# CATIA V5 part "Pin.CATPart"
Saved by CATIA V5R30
Part number: Pin
Bounding box of the stored display mesh (mm): x -10.997 to 10.997, y 0 to 38, z -10.885 to 10.885
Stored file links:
  D:\PROJECTS\CATIA V56R 2020\Resources\Parts File\c14_catia_v5_6r2020_prt\c14-catia-v5-6r2020-figr-14-26 & 27\Part & Asm\Pin.CATPart
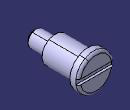
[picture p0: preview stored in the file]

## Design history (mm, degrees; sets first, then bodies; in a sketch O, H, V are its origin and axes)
Body1 (main body)
  Sketch1 on yz-plane, origin (0, 0, 0), H (0, 1, 0), V (0, 0, 1)
    line L1 (0, 0) -> (0, 5)
    line L2 (0, 5) -> (13, 5)
    line L3 (13, 5) -> (13, 8)
    line L4 (13, 8) -> (33, 8)
    line L5 (33, 8) -> (33, 11)
    line L6 (33, 11) -> (38, 11)
    line L7 (38, 11) -> (38, 0)
    point P7 (38, 0)
    line L8 (38, 0) -> (0, 0)
    distance L8 L6 = 11
    distance L4 L8 = 8
    length L8 = 38
    distance L2 L8 = 5
    length L6 = 5
    length L4 = 20
    vertical: L1 V, L3 V, L5 V, L7 V
    horizontal: L2 H, L4 H, L8 H, L6 H
    coincidence: P7 H
  Shaft1: profile Sketch1, axis edge of Sketch1, angle 360
  Chamfer1: length 1.5, angle 45, on 1 edge
  Fillet1: radius 1.5, on 1 edge
  Sketch2 on face of Shaft1, origin (0, 38, 0), H (-1, 0, 0), V (0, 0, 1)
    line L1 (-15.6575, 1.5) -> (20.3727, 1.5)
    line L2 (20.3727, 1.5) -> (20.3727, -1.5)
    line L3 (20.3727, -1.5) -> (-15.6575, -1.5)
    line L4 (-15.6575, -1.5) -> (-15.6575, 1.5)
    distance H L3 = 1.5
    length L4 = 3
    horizontal: L1 H, L3 H
    vertical: L2 V, L4 V
  Pocket1: profile Sketch2, direction (0, -1, 0), length 1.5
